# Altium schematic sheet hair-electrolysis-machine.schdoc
size 277 x 190 mm; Device: default297x210; Symbol: default297x210; Name: default297x210; Size: "A4"; Id: /; File: hair-electrolysis-machine; Sheet: /
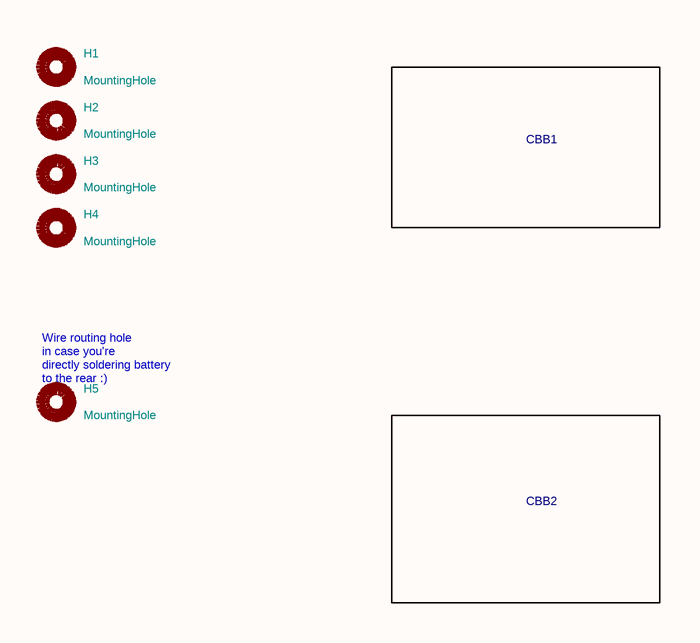
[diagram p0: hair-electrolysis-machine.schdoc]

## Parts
H1  value MountingHole  [MountingHole:MountingHole_3.2mm_M3]  (hidden comment: Mechanical_MountingHole)
H2  value MountingHole  [MountingHole:MountingHole_3.2mm_M3]  (hidden comment: Mechanical_MountingHole)
H3  value MountingHole  [MountingHole:MountingHole_3.2mm_M3]  (hidden comment: Mechanical_MountingHole)
H4  value MountingHole  [MountingHole:MountingHole_3.2mm_M3]  (hidden comment: Mechanical_MountingHole)
H5  value MountingHole  [MountingHole:MountingHole_2.5mm]  (hidden comment: Mechanical_MountingHole)

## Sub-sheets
CBB1 = power.schdoc: no entries  | Symbol: power; Sheetname: Power; Sheetfile: power.kicad_sch
CBB2 = mcu.schdoc: no entries  | Symbol: mcu; Sheetname: Mcu; Sheetfile: mcu.kicad_sch

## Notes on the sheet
- (near H5) Wire routing hole
  in case you're
  directly soldering battery
  to the rear :)

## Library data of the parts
H1 = Mechanical_MountingHole: Mounting Hole without connection; ki_fp_filters: MountingHole*; UniqueId: 42baa21c67f8a3af; Attribute1: H2; KiLib_Generator: mounting_hardware/mounting_hole; AddInBom: yes
H2 = Mechanical_MountingHole: Mounting Hole without connection; ki_fp_filters: MountingHole*; UniqueId: b7e18a508253e952; Attribute1: H2; KiLib_Generator: mounting_hardware/mounting_hole; AddInBom: yes
H3 = Mechanical_MountingHole: Mounting Hole without connection; ki_fp_filters: MountingHole*; UniqueId: 0c3ab7284e9cbe73; Attribute1: H2; KiLib_Generator: mounting_hardware/mounting_hole; AddInBom: yes
H4 = Mechanical_MountingHole: Mounting Hole without connection; ki_fp_filters: MountingHole*; UniqueId: a89bd88a2d6d819d; Attribute1: H2; KiLib_Generator: mounting_hardware/mounting_hole; AddInBom: yes
H5 = Mechanical_MountingHole: Mounting Hole without connection; ki_fp_filters: MountingHole*; UniqueId: 4dda69b6b957e2c3; Attribute1: H5; KiLib_Generator: mounting_hardware/mounting_hole; AddInBom: yes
